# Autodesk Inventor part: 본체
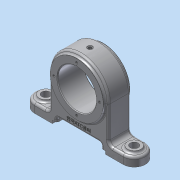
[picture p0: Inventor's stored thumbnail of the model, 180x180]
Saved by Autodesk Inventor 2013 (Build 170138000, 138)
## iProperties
Created: 2019-05
Part Number: 본체
Material: 알루미늄 6061
Document SubType Name: Modeling
Designer: dgall
Mass: 456.673 g
Surface Area: 318.792 cm^2
Volume: 168.514 cm^3
Density: 2.71 g/cm^3
Author: dgall
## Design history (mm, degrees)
sketch "스케치1"
  geometry: L1 (-18, 36)-(18, 36); L2 (18, 36)-(18, 0); L3 (18, 0)-(-18, 0); L4 (-18, 0)-(-18, 36); 2 further points
  constraints: 8 end point, 2 parallel, 1 coincident, 1 horizontal, 1 midpoint, 1 perpendicular
  dimensions: "d0" = 36 distance of L1.start L1.end; "d2" = 72 diameter of L1 L3
revolve "회전1" sketch "스케치1" stored, may be unused: angle "d3" = 90 deg
node "작업 평면1"
sketch "스케치2"
  geometry: L1 (-40, 0)-(-40, -60); L2 (-40, -60)-(40, -60); L3 (40, -60)-(40, 0); A1 r 40 centre (0, 0) between (40, 0) and (-40, 0); 1 further point
  constraints: 6 end point, 2 parallel, 2 point on circle, 1 centre point, 1 coincident, 1 perpendicular, 1 tangent, 1 vertical
  dimensions: "d4" = 80 diameter of A1; "d6" = 60 distance from line of L2 point (0, 0)
extrude "돌출1" join sketch "스케치2" stored distance "d7" = 30; taper "d8" = 0 deg
node "작업 평면2"
node "작업 평면3"
sketch "스케치3"
  geometry: L1 (-15, -40)-(15, -40) reference; L2 (15, -40)-(15, -60); L3 (-15, -40)-(-15, -60); A1 r 15 centre (0, -60) between (-15, -60) and (15, -60); 1 further point
  constraints: 4 end point, 2 point on circle, 2 tangent, 1 centre point, 1 parallel, 1 perpendicular
  dimensions: "d11" = 60 distance of A1.centre point (0, 0)
node "작업 평면4"
extrude "돌출2" join sketch "스케치3" distance "d12" = 12; taper "d13" = 0 deg
sketch "스케치4"
  geometry: C1 r 9 at (0, -60); A1 r 15 centre (0, -60) between (-15, -60) and (15, -60) reference; 1 further point
  constraints: 1 centre point, 1 coincident
  dimensions: "d14" = 18 diameter of C1
extrude "돌출3" join sketch "스케치4" distance "d16" = 3; taper "d17" = 0 deg
hole "구멍1" diameter "d20" = 11; stored, may be unused: countersink angle "d24" = 90 deg, drill point angle "d26" = 118 deg; dims "d18" = 10, "d19" = 10, "d21" = 6, "d22" = 4, "d23" = 2, "d25" = 8
sketch "스케치5" dims "d27" = 52
  geometry: L1 (-60, 60)-(-60, -60) reference; L2 (-60, 36)-(-56, 36); L3 (-56, 36)-(-56, 30); L4 (-56, 30)-(-50, 30); L5 (-50, 30)-(-50, -30); L6 (-50, -30)-(-56, -30); L7 (-56, -30)-(-56, -36); L8 (-56, -36)-(-60, -36); C1 r 36 at (0, 0) reference; C2 r 1.5 at (26, 0); 2 further points
  constraints: 14 end point, 3 horizontal alignment, 3 parallel, 2 perpendicular, 2 point on line, 1 centre point, 1 coincident, 1 collinear, 1 horizontal, 1 midpoint, 1 vertical alignment, 2 other
  dimensions: "d29" = 3 diameter of C2; "d30" = 72 distance between parallel lines of L8 L2; "d31" = 60 distance between parallel lines of L6 L4; "d32" = 4 distance between parallel lines of L1 L3; "d33" = 10 distance between parallel lines of L1 L5; "d34" = 36 distance from line of C1.centre L2
extrude "돌출4" cut sketch "스케치5" stored distance "d35" = 3; taper "d36" = 0 deg
sketch "스케치6"
  geometry: A1 r 26 centre (0, 0) between (25.957, 1.499) and (25.957, -1.499) reference; 1 further point
  constraints: 1 vertical alignment
  dimensions: "d37" = 31 distance of A1.centre point (0, 31)
hole "구멍2" sketch "스케치6" at (0, 31) diameter "d38" = 3.242; stored, may be unused: countersink angle "d42" = 90 deg, drill point angle "d44" = 120 deg; dims "d39" = 6, "d40" = 4, "d41" = 2, "d43" = 8
node "작업 평면5"
sketch "스케치7"
  geometry: 2 further points
  constraints: 1 coincident
hole "구멍3" sketch "스케치7" at (0, 0) diameter "d48" = 4.917; stored, may be unused: countersink angle "d52" = 90 deg, drill point angle "d54" = 120 deg; dims "d49" = 8, "d50" = 4, "d51" = 2, "d53" = 10
node "작업 평면6"
sketch "스케치8"
  geometry: L1 (-50, 30)-(-50, -30) reference; 2 further points
  constraints: 1 horizontal alignment, 1 other
  dimensions: "d74" = 7 distance from line of L1 point (-43, 0)
feature "엠보싱1" sketch "스케치8" dims "d0" = 36, "d2" = 72, "d11" = 60, "d75" = 0.5, "d76" = 0
fillet "모깎기1" dims "d77" = 6
fillet "모깎기2" dims "d78" = 3
fillet "모깎기3" dims "d79" = 3
fillet "모깎기4" dims "d80" = 3
fillet "모깎기5" dims "d81" = 3
fillet "모깎기6" dims "d82" = 3
chamfer "모따기1" distance "d83" = 1; stored, may be unused: second distance "d84" = 2, angle "d85" = 45 deg
sketch "스케치9"
  geometry: 2 further points
  constraints: 1 coincident
hole "구멍6" sketch "스케치9" at (0, 0) diameter "d86" = 7; stored, may be unused: countersink angle "d90" = 90 deg, drill point angle "d92" = 0 deg; dims "d87" = 8, "d88" = 4, "d89" = 2, "d91" = 1
hole "구멍7" diameter "d95" = 2; stored, may be unused: countersink angle "d99" = 90 deg, drill point angle "d101" = 0 deg; dims "d93" = 10, "d94" = 10, "d96" = 8, "d97" = 4, "d98" = 2, "d100" = 1
node "솔리드1"
mirror "대칭1"
pattern_circular "원형 패턴1" dims angle "d46" = 360 deg
mirror "대칭2"
other parameters: "d73" = 53.5
